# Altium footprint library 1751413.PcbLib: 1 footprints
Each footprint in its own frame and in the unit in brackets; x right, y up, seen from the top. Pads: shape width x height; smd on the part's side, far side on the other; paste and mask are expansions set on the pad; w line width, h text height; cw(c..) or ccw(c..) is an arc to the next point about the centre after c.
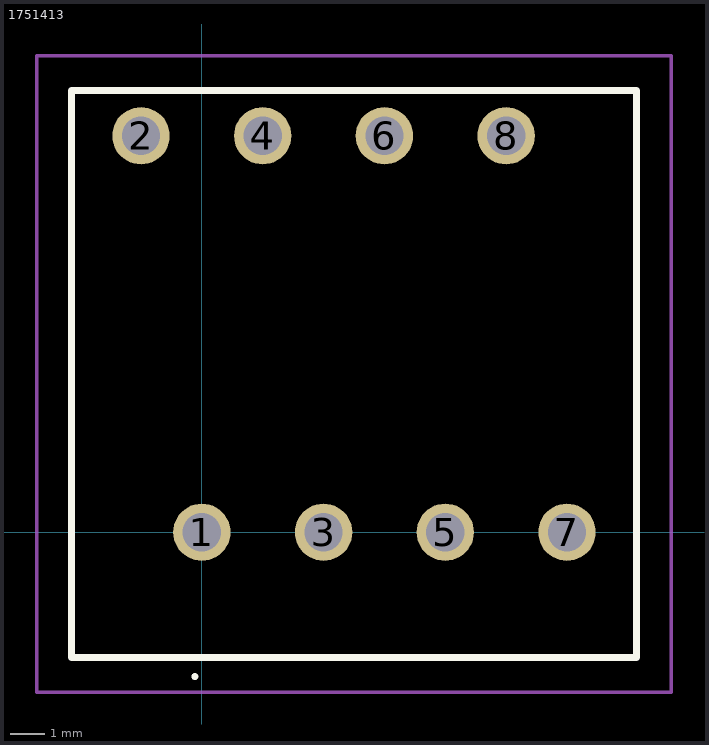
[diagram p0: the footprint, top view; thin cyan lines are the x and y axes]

## 1751413 [mm]
pads (8):
  round 1.65 hole 1.1: 1(0,0) 2(-1.75,11.4) 3(3.5,0) 4(1.75,11.4) 5(7,0) 6(5.25,11.4) 7(10.5,0) 8(8.75,11.4)
Top Overlay:
  lines w0.1: -0.2,-4.2 -0.2,-4.2 ; -0.2,-4.2 ccw(c-0.2,-4.15) -0.2,-4.1 ; -0.2,-4.2 cw(c-0.2,-4.15) -0.2,-4.1 ; -0.2,-4.1 -0.2,-4.1
  lines w0.2: -3.75,-3.6 12.5,-3.6 12.5,12.7 -3.75,12.7 -3.75,-3.6
Mechanical 15:
  lines w0.1: -3.75,-3.6 12.5,-3.6 12.5,12.7 -3.75,12.7 -3.75,-3.6
Mechanical 20:
  lines w0.1: -4.75,-4.6 13.5,-4.6 13.5,13.7 -4.75,13.7 -4.75,-4.6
